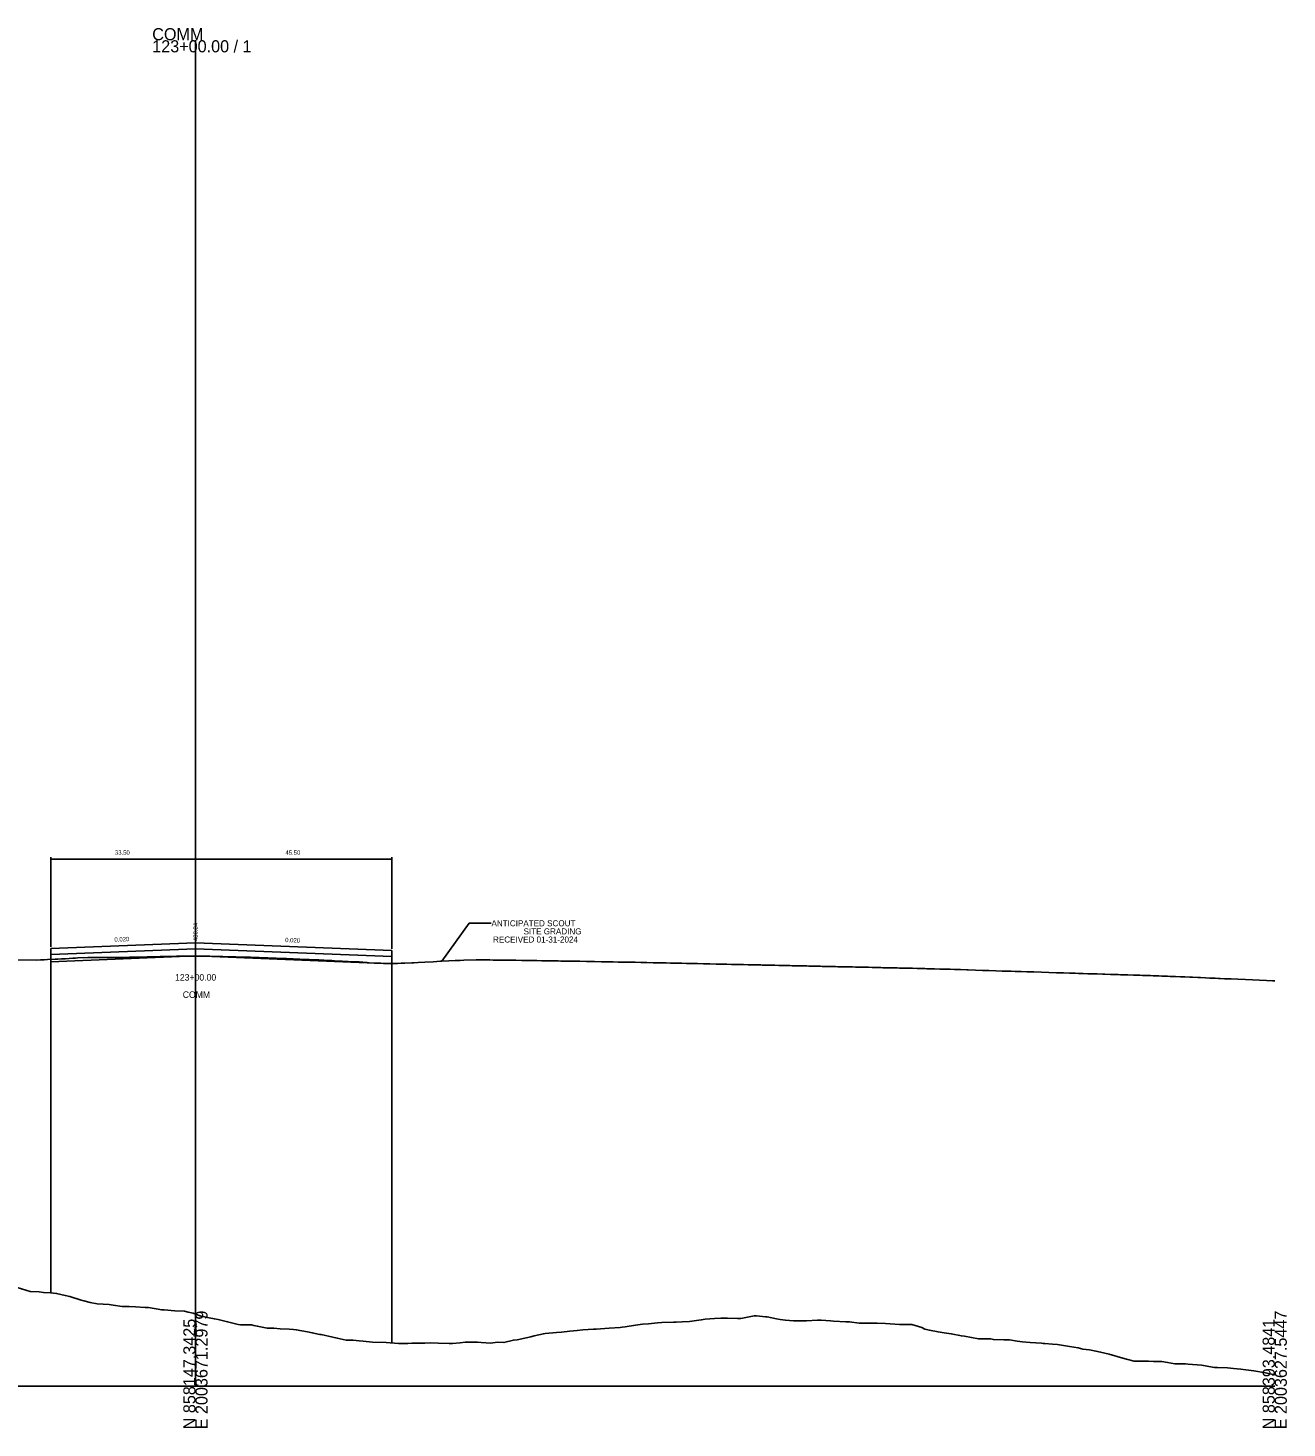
# Model space of a CAD drawing. Extents: x 2058594 to 2062449, y 841632 to 858028.
# Drawn here: x 2061157.7 to 2061449.4, y 857703.8 to 858028.1 of the extents above; entities that cross this region are included whole.
import ezdxf

# ---------------------------------------------------------------- set-up
doc = ezdxf.new("R2010")
doc.units = 0
for name, color, linetype in [('RD_DDB_Profile_Elev', 7, 'Continuous'), ('RD_GPK_XS_Cell', 7, 'Continuous'), ('RD_XS_Base', 7, 'Continuous'), ('RD_XS_EwShp1', 7, 'Continuous'), ('RD_XS_ExGround', 7, 'Continuous'), ('RD_XS_MatchLine', 7, 'Continuous'), ('RD_XS_Pave', 7, 'Continuous'), ('RD_XS_PaveShd', 7, 'Continuous'), ('RD_XS_TX_Elev_EX', 7, 'Continuous'), ('RD_XS_TX_Elev_PR', 7, 'Continuous'), ('RD_XS_TX_Misc', 7, 'Continuous'), ('RD_XS_TX_Slope', 7, 'Continuous'), ('RD_XS_TX_Station', 7, 'Continuous')]:
    doc.layers.add(name, color=color, linetype=linetype)

msp = doc.modelspace()

# ---------------------------------------------------------------- linework, layer by layer
at = {"layer": 'RD_DDB_Profile_Elev'}
for points in [[(2061265.03, 857820.74), (2061259.91, 857820.74), (2061253.57, 857811.91)], [(2061153, 857812.26), (2061159.75, 857812.21), (2061160.64, 857812.25), (2061161.48, 857812.27), (2061162.25, 857812.3), (2061164.03, 857812.38), (2061164.66, 857812.42), (2061165.49, 857812.47), (2061166.4, 857812.52), (2061167.29, 857812.58), (2061168.08, 857812.63), (2061168.74, 857812.67), (2061169.25, 857812.7), (2061171.61, 857812.77), (2061172.04, 857812.77), (2061172.57, 857812.77), (2061173.18, 857812.77), (2061173.83, 857812.76), (2061174.49, 857812.76), (2061175.12, 857812.76), (2061175.68, 857812.76), (2061176.15, 857812.76), (2061176.48, 857812.76), (2061176.79, 857812.76), (2061177.58, 857812.78), (2061177.97, 857812.78), (2061178.7, 857812.8), (2061179.15, 857812.8), (2061179.77, 857812.82), (2061180.25, 857812.82), (2061180.72, 857812.83), (2061181.27, 857812.85), (2061181.76, 857812.84), (2061182.49, 857812.87), (2061182.98, 857812.87), (2061183.86, 857812.89), (2061184.32, 857812.89), (2061185.3, 857812.92), (2061185.71, 857812.92), (2061186.73, 857812.96), (2061187.08, 857812.95), (2061188.37, 857812.99), (2061189.72, 857813.02), (2061190.75, 857813.04), (2061192.12, 857813.08), (2061192.44, 857813.08), (2061192.8, 857813.09), (2061193.4, 857813.11), (2061194.23, 857813.12), (2061197.74, 857813.13), (2061198.24, 857813.12), (2061198.85, 857813.11), (2061199.23, 857813.11), (2061199.88, 857813.08), (2061200.82, 857813.05), (2061201.26, 857813.05), (2061202.4, 857813.01), (2061202.86, 857813.01), (2061204.12, 857812.96), (2061204.56, 857812.96), (2061205.86, 857812.92), (2061208.46, 857812.88), (2061208.77, 857812.87), (2061209.24, 857812.85), (2061209.86, 857812.82), (2061211.25, 857812.78), (2061212.03, 857812.75), (2061213.28, 857812.71), (2061214.18, 857812.67), (2061215.23, 857812.63), (2061216.23, 857812.59), (2061217.04, 857812.56), (2061217.59, 857812.54), (2061218.62, 857812.49), (2061219.12, 857812.48), (2061220.1, 857812.43), (2061220.73, 857812.41), (2061221.58, 857812.37), (2061222.28, 857812.34), (2061222.88, 857812.32), (2061223.51, 857812.29), (2061224.22, 857812.26), (2061225.1, 857812.22), (2061226.22, 857812.16), (2061226.86, 857812.14), (2061228.14, 857812.07), (2061228.7, 857812.05), (2061230.08, 857811.98), (2061230.53, 857811.96), (2061231.91, 857811.89), (2061233.26, 857811.82), (2061234.43, 857811.76), (2061235.27, 857811.71), (2061236.29, 857811.64), (2061236.76, 857811.59), (2061237.95, 857811.51), (2061238.38, 857811.49), (2061238.93, 857811.48), (2061239.48, 857811.46), (2061240.41, 857811.43), (2061241.95, 857811.4), (2061242.52, 857811.42), (2061243.31, 857811.44), (2061244.19, 857811.47), (2061245.02, 857811.5), (2061246.66, 857811.56), (2061247.07, 857811.58), (2061248.13, 857811.64), (2061249.68, 857811.72), (2061251.55, 857811.82), (2061253.25, 857811.91), (2061253.57, 857811.91), (2061255.21, 857812), (2061256.64, 857812.07), (2061257.82, 857812.13), (2061258.71, 857812.18), (2061261.56, 857812.26), (2061261.95, 857812.26), (2061262.5, 857812.25), (2061263.18, 857812.24), (2061263.93, 857812.23), (2061264.7, 857812.22), (2061265.44, 857812.21), (2061266.1, 857812.2), (2061266.6, 857812.2), (2061267.06, 857812.19), (2061267.51, 857812.19), (2061268.2, 857812.18), (2061269.09, 857812.16), (2061269.45, 857812.16), (2061270.74, 857812.15), (2061272.12, 857812.12), (2061273.33, 857812.1), (2061273.63, 857812.1), (2061273.99, 857812.1), (2061275.2, 857812.07), (2061275.59, 857812.07), (2061276.75, 857812.05), (2061277.14, 857812.05), (2061278.2, 857812.03), (2061278.58, 857812.02), (2061279.48, 857812.01), (2061280.16, 857811.99), (2061280.5, 857811.99), (2061281.18, 857811.98), (2061281.49, 857811.98), (2061282.67, 857811.96), (2061283.99, 857811.93), (2061285.55, 857811.91), (2061287.09, 857811.88), (2061288.94, 857811.85), (2061290.55, 857811.82), (2061292.08, 857811.79), (2061293.27, 857811.77), (2061294.45, 857811.75), (2061295.34, 857811.73), (2061296.05, 857811.72), (2061297.1, 857811.7), (2061298.35, 857811.68), (2061299.7, 857811.65), (2061301.09, 857811.62), (2061302.52, 857811.59), (2061303.96, 857811.56), (2061305.54, 857811.53), (2061306.52, 857811.51), (2061307.58, 857811.48), (2061308.36, 857811.47), (2061309.19, 857811.45), (2061310.26, 857811.43), (2061311.41, 857811.4), (2061312.78, 857811.37), (2061314.21, 857811.34), (2061315.65, 857811.31), (2061317.14, 857811.28), (2061318.42, 857811.25), (2061319.61, 857811.23), (2061320.68, 857811.2), (2061321.58, 857811.18), (2061322.3, 857811.17), (2061323.5, 857811.14), (2061324.56, 857811.12), (2061324.86, 857811.11), (2061326.01, 857811.09), (2061326.32, 857811.08), (2061327.49, 857811.06), (2061327.79, 857811.05), (2061329.42, 857811.01), (2061330.73, 857810.99), (2061331.68, 857810.97), (2061331.99, 857810.96), (2061332.79, 857810.94), (2061333.17, 857810.93), (2061333.78, 857810.92), (2061334.22, 857810.91), (2061334.76, 857810.9), (2061335.46, 857810.88), (2061335.94, 857810.87), (2061336.74, 857810.86), (2061337.24, 857810.85), (2061338.11, 857810.83), (2061338.62, 857810.82), (2061339.52, 857810.8), (2061340, 857810.79), (2061340.9, 857810.77), (2061341.32, 857810.76), (2061341.66, 857810.75), (2061342.52, 857810.73), (2061342.84, 857810.72), (2061343.63, 857810.71), (2061344.06, 857810.7), (2061344.76, 857810.68), (2061345.29, 857810.67), (2061345.88, 857810.66), (2061346.49, 857810.65), (2061346.93, 857810.64), (2061347.4, 857810.63), (2061348.07, 857810.61), (2061348.71, 857810.6), (2061349.42, 857810.58), (2061350.17, 857810.56), (2061350.89, 857810.55), (2061351.7, 857810.53), (2061352.41, 857810.52), (2061353.24, 857810.5), (2061353.89, 857810.48), (2061354.46, 857810.47), (2061355.27, 857810.45), (2061355.72, 857810.44), (2061356.19, 857810.43), (2061356.94, 857810.42), (2061357.59, 857810.4), (2061358.26, 857810.39), (2061359.07, 857810.37), (2061359.62, 857810.35), (2061360.56, 857810.33), (2061360.98, 857810.32), (2061362.57, 857810.29), (2061363.66, 857810.26), (2061364.01, 857810.25), (2061364.4, 857810.24), (2061365.5, 857810.22), (2061365.9, 857810.21), (2061366.97, 857810.18), (2061367.34, 857810.17), (2061367.69, 857810.16), (2061368.96, 857810.13), (2061369.8, 857810.11), (2061370.67, 857810.09), (2061371.31, 857810.07), (2061372.36, 857810.03), (2061373.69, 857809.99), (2061375.22, 857809.94), (2061375.53, 857809.93), (2061377.18, 857809.88), (2061378.85, 857809.82), (2061380.3, 857809.77), (2061381.9, 857809.72), (2061383.34, 857809.67), (2061384.55, 857809.63), (2061385.46, 857809.6), (2061386.37, 857809.57), (2061387.74, 857809.53), (2061389.06, 857809.49), (2061390.71, 857809.44), (2061392.45, 857809.38), (2061394.21, 857809.33), (2061396, 857809.27), (2061397.55, 857809.22), (2061399, 857809.18), (2061399.99, 857809.15), (2061400.3, 857809.14), (2061401.03, 857809.12), (2061401.78, 857809.09), (2061402.17, 857809.08), (2061403.19, 857809.05), (2061403.65, 857809.03), (2061404.84, 857809), (2061405.35, 857808.98), (2061406.64, 857808.94), (2061407.19, 857808.93), (2061408.48, 857808.89), (2061409.03, 857808.87), (2061410.27, 857808.83), (2061410.76, 857808.82), (2061411.89, 857808.78), (2061412.52, 857808.76), (2061413.76, 857808.72), (2061414.12, 857808.71), (2061414.9, 857808.69), (2061415.3, 857808.68), (2061415.86, 857808.66), (2061416.58, 857808.64), (2061417.02, 857808.63), (2061417.34, 857808.62), (2061417.74, 857808.61), (2061418.35, 857808.58), (2061418.76, 857808.57), (2061419.25, 857808.55), (2061419.69, 857808.54), (2061420.37, 857808.51), (2061420.79, 857808.49), (2061421.65, 857808.45), (2061422.29, 857808.43), (2061423.54, 857808.38), (2061424.67, 857808.33), (2061425.11, 857808.31), (2061425.67, 857808.29), (2061426.87, 857808.23), (2061427.48, 857808.21), (2061428.7, 857808.15), (2061429.3, 857808.13), (2061430.44, 857808.08), (2061431.46, 857808.03), (2061431.97, 857808.01), (2061432.73, 857807.98), (2061433.47, 857807.94), (2061433.89, 857807.93), (2061434.87, 857807.88), (2061435.21, 857807.87), (2061436.39, 857807.82), (2061437.99, 857807.75), (2061439.71, 857807.67), (2061441.35, 857807.6), (2061443.02, 857807.53), (2061444.64, 857807.46), (2061446.01, 857807.41), (2061446.51, 857807.39)]]:
    msp.add_lwpolyline(points, dxfattribs=at)
at = {"layer": 'RD_GPK_XS_Cell'}
for p, q in [((2061196.51, 857713.53), (2061196.51, 858025.22)), ((2060946.51, 857713.53), (2061196.51, 857713.53)), ((2061196.51, 857713.53), (2061446.51, 857713.53))]:
    msp.add_line(p, q, dxfattribs=at)
at = {"layer": 'RD_XS_Base'}
for p, q in [((2061163.01, 857811.83), (2061163.01, 857813.49)), ((2061163.01, 857811.83), (2061196.51, 857813.17)), ((2061196.51, 857813.17), (2061242.01, 857811.35)), ((2061242.01, 857811.35), (2061242.01, 857813.01))]:
    msp.add_line(p, q, dxfattribs=at)
at = {"layer": 'RD_XS_EwShp1'}
for p, q in [((2061163.01, 857811.83), (2061196.51, 857813.17)), ((2061163.01, 857735.15), (2061163.01, 857811.83)), ((2061196.51, 857813.17), (2061242.01, 857811.35)), ((2061242.01, 857723.55), (2061242.01, 857811.35))]:
    msp.add_line(p, q, dxfattribs=at)
at = {"layer": 'RD_XS_ExGround'}
msp.add_lwpolyline([(2061155.25, 857736.41), (2061158.25, 857735.46), (2061160.35, 857735.37), (2061161.3, 857735.25), (2061162.93, 857735.16), (2061164.35, 857735), (2061166.37, 857734.55), (2061167.39, 857734.29), (2061170.07, 857733.43), (2061170.7, 857733.27), (2061172.13, 857732.93), (2061173.78, 857732.61), (2061176.54, 857732.42), (2061177.49, 857732.29), (2061179.58, 857731.95), (2061181.19, 857731.97), (2061182.63, 857731.9), (2061184.9, 857731.74), (2061185.68, 857731.74), (2061188.73, 857731.2), (2061189.28, 857731.17), (2061191.77, 857730.99), (2061193.98, 857730.88), (2061194.82, 857730.65), (2061196.02, 857730.42), (2061196.51, 857730.23), (2061197.87, 857729.72), (2061199.73, 857729.31), (2061200.92, 857729.08), (2061201.75, 857728.95), (2061203.96, 857728.43), (2061206.42, 857727.83), (2061207.01, 857727.72), (2061209.51, 857727.72), (2061210.06, 857727.54), (2061210.84, 857727.45), (2061213.11, 857726.96), (2061214.69, 857726.96), (2061216.15, 857726.8), (2061218.26, 857726.69), (2061219.2, 857726.64), (2061219.86, 857726.57), (2061222.45, 857726.09), (2061223.57, 857725.88), (2061225.3, 857725.52), (2061225.67, 857725.45), (2061228.34, 857724.85), (2061229.38, 857724.66), (2061231.39, 857724.21), (2061233.08, 857724.15), (2061234.44, 857724), (2061235.39, 857723.92), (2061237.49, 857723.75), (2061240.71, 857723.66), (2061243.58, 857723.43), (2061245.74, 857723.42), (2061246.63, 857723.45), (2061247.91, 857723.48), (2061249.68, 857723.51), (2061250.91, 857723.52), (2061252.72, 857723.47), (2061255.32, 857723.39), (2061255.77, 857723.39), (2061256.09, 857723.4), (2061257.86, 857723.59), (2061259.03, 857723.7), (2061261.87, 857723.7), (2061262.73, 857723.62), (2061264.92, 857723.48), (2061266.44, 857723.74), (2061267.96, 857723.6), (2061270.15, 857724.2), (2061271.01, 857724.23), (2061274.2, 857724.98), (2061275, 857725.18), (2061277.11, 857725.67), (2061277.56, 857725.7), (2061280.15, 857725.92), (2061281.27, 857726.06), (2061283.2, 857726.27), (2061284.97, 857726.41), (2061286.25, 857726.54), (2061288.68, 857726.71), (2061289.3, 857726.74), (2061292.34, 857726.95), (2061294.9, 857727.13), (2061295.39, 857727.16), (2061296.09, 857727.27), (2061298.44, 857727.63), (2061300.08, 857727.85), (2061301.49, 857727.99), (2061303.51, 857728.19), (2061304.53, 857728.25), (2061307.21, 857728.33), (2061307.84, 857728.36), (2061309.29, 857728.43), (2061310.92, 857728.51), (2061313.68, 857728.87), (2061314.62, 857729.03), (2061316.72, 857729.19), (2061318.19, 857729.25), (2061319.77, 857729.24), (2061322.04, 857729.2), (2061322.82, 857729.18), (2061325.95, 857729.83), (2061326.44, 857729.79), (2061328.54, 857729.55), (2061328.91, 857729.55), (2061331.13, 857729.14), (2061331.96, 857728.99), (2061333.16, 857728.79), (2061335.01, 857728.65), (2061336.86, 857728.68), (2061338.06, 857728.67), (2061340.57, 857728.83), (2061341.1, 857728.82), (2061341.48, 857728.81), (2061343.58, 857728.64), (2061344.28, 857728.58), (2061347.2, 857728.44), (2061347.98, 857728.41), (2061350.25, 857728.09), (2061351.83, 857728.13), (2061353.3, 857728.15), (2061354.42, 857728.13), (2061356.34, 857728), (2061359.59, 857727.8), (2061360.73, 857727.81), (2061362.44, 857727.83), (2061364.77, 857727.08), (2061365.49, 857726.73), (2061366.51, 857726.47), (2061368.53, 857726.07), (2061369.94, 857725.87), (2061371.58, 857725.67), (2061373.93, 857725.16), (2061374.63, 857725.08), (2061377.87, 857724.51), (2061380.29, 857724.48), (2061380.72, 857724.46), (2061381.34, 857724.33), (2061383.77, 857724.23), (2061385.05, 857724.23), (2061386.82, 857723.94), (2061388.06, 857723.8), (2061389.87, 857723.6), (2061392.46, 857723.45), (2061392.91, 857723.44), (2061393.23, 857723.4), (2061395.02, 857723.28), (2061396.17, 857723.18), (2061399.01, 857722.69), (2061400.99, 857722.38), (2061402.06, 857722.11), (2061403.58, 857721.92), (2061405.1, 857721.64), (2061406.17, 857721.42), (2061408.15, 857720.95), (2061411.34, 857720.02), (2061412.16, 857719.8), (2061413.93, 857719.35), (2061414.25, 857719.29), (2061414.7, 857719.3), (2061417.29, 857719.35), (2061418.4, 857719.26), (2061420.34, 857719.23), (2061421.69, 857719.04), (2061423.39, 857718.71), (2061425.82, 857718.68), (2061426.44, 857718.62), (2061429.52, 857718.36), (2061432.53, 857717.86), (2061433.23, 857717.82), (2061435.58, 857717.79), (2061436.94, 857717.64), (2061438.63, 857717.49), (2061439.81, 857717.31), (2061441.68, 857717.04), (2061444.35, 857716.63), (2061444.72, 857716.55), (2061446.51, 857716.16)], dxfattribs=at)
at = {"layer": 'RD_XS_MatchLine'}
for p, q in [((2061163.01, 857814.86), (2061163.01, 857735.15)), ((2061242.01, 857814.38), (2061242.01, 857723.55))]:
    msp.add_line(p, q, dxfattribs=at)
at = {"layer": 'RD_XS_Pave'}
for p, q in [((2061163.01, 857814.86), (2061196.51, 857816.2)), ((2061163.01, 857813.49), (2061196.51, 857814.83)), ((2061196.51, 857816.2), (2061242.01, 857814.38)), ((2061196.51, 857814.83), (2061242.01, 857813.01))]:
    msp.add_line(p, q, dxfattribs=at)
at = {"layer": 'RD_XS_PaveShd'}
for p, q in [((2061163.01, 857813.49), (2061163.01, 857814.86)), ((2061242.01, 857813.01), (2061242.01, 857814.38))]:
    msp.add_line(p, q, dxfattribs=at)
at = {"layer": 'RD_XS_TX_Misc'}
for p, q in [((2061163.01, 857836), (2061163.01, 857815.26)), ((2061163.01, 857835.6), (2061196.51, 857835.6)), ((2061196.51, 857836), (2061196.51, 857816.6)), ((2061196.51, 857835.6), (2061242.01, 857835.6)), ((2061242.01, 857836), (2061242.01, 857814.78))]:
    msp.add_line(p, q, dxfattribs=at)

# ---------------------------------------------------------------- texts
at = {"layer": 'RD_DDB_Profile_Elev'}
for s, p in [('ANTICIPATED SCOUT', (2061265.08, 857820.03)), ('RECEIVED 01-31-2024', (2061265.45, 857816.26)), ('SITE GRADING', (2061272.52, 857818.14))]:
    msp.add_text(s, height=1.4, dxfattribs=at).set_placement(p)
at = {"layer": 'RD_GPK_XS_Cell'}
for s, p in [('COMM', (2061186.51, 858025.22)), ('123+00.00 / 1', (2061186.51, 858022.42))]:
    msp.add_text(s, height=2.8, dxfattribs=at).set_placement(p)
for s, p in [('E 2003671.2979', (2061199.31, 857703.53)), ('E 2003627.5447', (2061449.31, 857703.53)), ('N 858147.3425', (2061196.51, 857703.53)), ('N 858393.4841', (2061446.51, 857703.53))]:
    msp.add_text(s, height=2.8, rotation=90, dxfattribs=at).set_placement(p)
at = {"layer": 'RD_XS_TX_Elev_EX'}
msp.add_text('437.35', height=0.8, rotation=270, dxfattribs=at).set_placement((2061196.11, 857728.23))
at = {"layer": 'RD_XS_TX_Elev_PR'}
msp.add_text(' 480.34', height=1, rotation=90, dxfattribs=at).set_placement((2061197.01, 857816.2))
at = {"layer": 'RD_XS_TX_Misc'}
for s, p in [('33.50', (2061177.85, 857836.6)), ('45.50', (2061217.35, 857836.6))]:
    msp.add_text(s, height=1, dxfattribs=at).set_placement(p)
at = {"layer": 'RD_XS_TX_Slope'}
for rotation, p in [(2.2906, (2061177.76, 857816.45)), (357.7094, (2061217.28, 857816.37))]:
    msp.add_text('0.020', height=1, rotation=rotation, dxfattribs=at).set_placement(p)
at = {"layer": 'RD_XS_TX_Station'}
for s, p in [('123+00.00', (2061191.79, 857807.45)), ('COMM', (2061193.57, 857803.45))]:
    msp.add_text(s, height=1.5, dxfattribs=at).set_placement(p)

doc.saveas('drawing.dxf')
